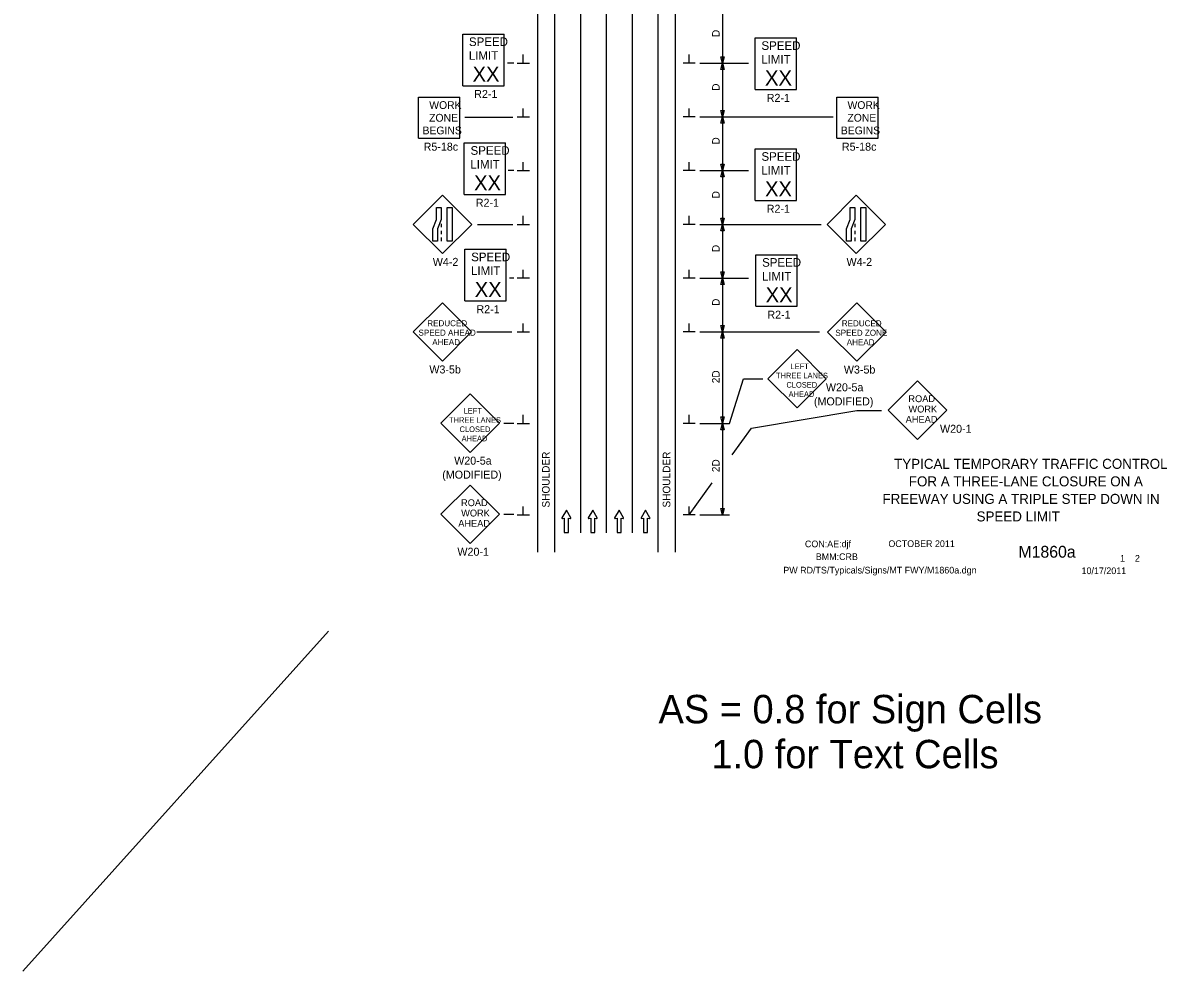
# Model space of a CAD drawing. Extents: x 16364 to 18480, y 5564 to 6927.
# Drawn here: x 16364 to 17427, y 5564 to 6446 of the extents above; entities that cross this region are included whole.
import ezdxf

# ---------------------------------------------------------------- set-up
doc = ezdxf.new("R2010")
doc.units = 0
for name, color, linetype in [('ALI_LEGAL_EX', 7, 'Continuous'), ('BORDER', 7, 'Continuous'), ('BORDER_SIGNAL_WO', 7, 'Continuous'), ('MT_SCRATCH_LEVEL_E', 7, 'Continuous'), ('PAVT_EDGE_EX', 7, 'Continuous'), ('TRAFFIC_SIGNS_PR', 7, 'Continuous'), ('TYPICAL_TEXT_DIMEN_PR', 7, 'Continuous')]:
    doc.layers.add(name, color=color, linetype=linetype)

msp = doc.modelspace()

# ---------------------------------------------------------------- linework, layer by layer
at = {"layer": 'ALI_LEGAL_EX'}
for p, q in [((16882, 6876.4), (16882, 5996.4)), ((16906, 6876.4), (16906, 5996.4)), ((16930, 6876.4), (16930, 5996.4))]:
    msp.add_line(p, q, dxfattribs=at)
for points in [[(16882, 6396.5), (16882, 6371.5)], [(16906, 6396.5), (16906, 6371.5)], [(16930, 6396.5), (16930, 6371.5)], [(16882, 6296.5), (16882, 6271.5)], [(16906, 6296.5), (16906, 6271.5)], [(16930, 6296.5), (16930, 6271.5)], [(16882, 6196.5), (16882, 6171.5)], [(16906, 6196.5), (16906, 6171.5)], [(16930, 6196.5), (16930, 6171.5)], [(16882, 6096.5), (16882, 6071.5)], [(16906, 6096.5), (16906, 6071.5)], [(16930, 6096.5), (16930, 6071.5)], [(16882, 5996.5), (16882, 5971.5)], [(16906, 5996.5), (16906, 5971.5)], [(16930, 5996.5), (16930, 5971.5)]]:
    msp.add_lwpolyline(points, dxfattribs=at)
at = {"layer": 'MT_SCRATCH_LEVEL_E'}
for p, q in [((16868.9, 5992.7), (16864.8, 5985.5)), ((16873, 5985.5), (16868.9, 5992.7)), ((16893.4, 5992.7), (16889.3, 5985.5)), ((16897.6, 5985.5), (16893.4, 5992.7)), ((16917.9, 5992.7), (16913.8, 5985.5)), ((16922.1, 5985.5), (16917.9, 5992.7)), ((16942.5, 5992.7), (16938.4, 5985.5)), ((16946.6, 5985.5), (16942.5, 5992.7)), ((16865.2, 5984.8), (16867, 5985.1)), ((16867, 5985.1), (16867, 5971.9)), ((16870.8, 5971.9), (16870.8, 5985.1)), ((16870.8, 5985.1), (16872.5, 5984.8)), ((16889.8, 5984.8), (16891.6, 5985.1)), ((16891.6, 5985.1), (16891.6, 5971.9)), ((16895.3, 5971.9), (16895.3, 5985.1)), ((16895.3, 5985.1), (16897.1, 5984.8)), ((16914.3, 5984.8), (16916.1, 5985.1)), ((16916.1, 5985.1), (16916.1, 5971.9)), ((16919.8, 5971.9), (16919.8, 5985.1)), ((16919.8, 5985.1), (16921.6, 5984.8)), ((16938.9, 5984.8), (16940.6, 5985.1)), ((16940.6, 5985.1), (16940.6, 5971.9)), ((16944.4, 5971.9), (16944.4, 5985.1)), ((16944.4, 5985.1), (16946.2, 5984.8)), ((16867, 5971.9), (16870.8, 5971.9)), ((16891.6, 5971.9), (16895.3, 5971.9)), ((16916.1, 5971.9), (16919.8, 5971.9)), ((16940.6, 5971.9), (16944.4, 5971.9))]:
    msp.add_line(p, q, dxfattribs=at)
for centre, start, end in [((16865.2, 5985.3), 150.4248, 279.9638), ((16872.6, 5985.3), 260.0362, 29.7731), ((16889.7, 5985.3), 150.4248, 279.9638), ((16897.1, 5985.3), 260.0362, 29.7731), ((16914.2, 5985.3), 150.4248, 279.9638), ((16921.7, 5985.3), 260.0362, 29.7731), ((16938.8, 5985.3), 150.4248, 279.9638), ((16946.2, 5985.3), 260.0362, 29.7731)]:
    msp.add_arc(centre, 0.463, start, end, dxfattribs=at)
at = {"layer": 'PAVT_EDGE_EX'}
for p, q in [((16842, 6926.7), (16842, 5953.6)), ((16858, 6926.7), (16858, 5953.6)), ((16954, 6926.7), (16954, 5953.6)), ((16970, 6926.7), (16970, 5953.6))]:
    msp.add_line(p, q, dxfattribs=at)
at = {"layer": 'TRAFFIC_SIGNS_PR'}
for p, q in [((16772.6, 6435.2), (16811, 6435.2)), ((16772.6, 6387.2), (16772.6, 6435.2)), ((16811, 6387.2), (16811, 6435.2)), ((17044.5, 6431.6), (17082.9, 6431.6)), ((17044.5, 6383.6), (17044.5, 6431.6)), ((17082.9, 6383.6), (17082.9, 6431.6)), ((16772.6, 6387.2), (16811, 6387.2)), ((17044.5, 6383.6), (17082.9, 6383.6)), ((16731.4, 6338.3), (16731.4, 6376.7)), ((16731.4, 6376.7), (16769.8, 6376.7)), ((16769.8, 6338.3), (16769.8, 6376.7)), ((17120.3, 6338.3), (17120.3, 6376.7)), ((17120.3, 6376.7), (17158.7, 6376.7)), ((17158.7, 6338.3), (17158.7, 6376.7)), ((16731.4, 6338.3), (16769.8, 6338.3)), ((16774, 6334.1), (16812.4, 6334.1)), ((16774, 6286.1), (16774, 6334.1)), ((16812.4, 6286.1), (16812.4, 6334.1)), ((17120.3, 6338.3), (17158.7, 6338.3)), ((17044.5, 6328.5), (17082.9, 6328.5)), ((17044.5, 6280.5), (17044.5, 6328.5)), ((17082.9, 6280.5), (17082.9, 6328.5)), ((16753.7, 6285.4), (16726.6, 6258.3)), ((16780.9, 6258.3), (16753.7, 6285.4)), ((16774, 6286.1), (16812.4, 6286.1)), ((17044.5, 6280.5), (17082.9, 6280.5)), ((17138.4, 6285.4), (17111.3, 6258.3)), ((17165.6, 6258.3), (17138.4, 6285.4)), ((16726.6, 6258.3), (16753.7, 6231.1)), ((16752.5, 6258.8), (16752.5, 6255.6)), ((16753.7, 6231.1), (16780.9, 6258.3)), ((17111.3, 6258.3), (17138.4, 6231.1)), ((17137.2, 6258.8), (17137.2, 6255.6)), ((17138.4, 6231.1), (17165.6, 6258.3)), ((16752.5, 6252.4), (16752.5, 6249.2)), ((16752.5, 6246), (16752.5, 6242.8)), ((17137.2, 6252.4), (17137.2, 6249.2)), ((17137.2, 6246), (17137.2, 6242.8)), ((16774.6, 6235.1), (16813, 6235.1)), ((16774.6, 6187.1), (16774.6, 6235.1)), ((16813, 6187.1), (16813, 6235.1)), ((17045.1, 6230.1), (17083.5, 6230.1)), ((17045.1, 6182.1), (17045.1, 6230.1)), ((17083.5, 6182.1), (17083.5, 6230.1)), ((16753.6, 6185.4), (16726.4, 6158.3)), ((16780.7, 6158.3), (16753.6, 6185.4)), ((16774.6, 6187.1), (16813, 6187.1)), ((17045.1, 6182.1), (17083.5, 6182.1)), ((17139, 6185.3), (17111.8, 6158.2)), ((17166.1, 6158.2), (17139, 6185.3)), ((16726.4, 6158.3), (16753.6, 6131.1)), ((16753.6, 6131.1), (16780.7, 6158.3)), ((17111.8, 6158.2), (17139, 6131)), ((17139, 6131), (17166.1, 6158.2)), ((17083.4, 6141.9), (17056.2, 6114.8)), ((17110.5, 6114.8), (17083.4, 6141.9)), ((17056.2, 6114.8), (17083.4, 6087.6)), ((17083.4, 6087.6), (17110.5, 6114.8)), ((17195.4, 6112.7), (17168.2, 6085.5)), ((17222.6, 6085.5), (17195.4, 6112.7)), ((16779.5, 6100.6), (16752.3, 6073.5)), ((16806.6, 6073.5), (16779.5, 6100.6)), ((17168.2, 6085.5), (17195.4, 6058.3)), ((17195.4, 6058.3), (17222.6, 6085.5)), ((16752.3, 6073.5), (16779.5, 6046.3)), ((16779.5, 6046.3), (16806.6, 6073.5)), ((16779.4, 6015.9), (16752.3, 5988.8)), ((16806.6, 5988.8), (16779.4, 6015.9)), ((16752.3, 5988.8), (16779.4, 5961.6)), ((16779.4, 5961.6), (16806.6, 5988.8))]:
    msp.add_line(p, q, dxfattribs=at)
for points in [[(16752.5, 6274), (16752.5, 6262.9), (16749.2, 6254), (16749.2, 6242.8), (16744.7, 6242.8), (16744.7, 6254), (16748, 6262.9), (16748, 6274)], [(16762.6, 6274), (16762.6, 6242.8), (16758.1, 6242.8), (16758.1, 6274)], [(17137.2, 6274), (17137.2, 6262.9), (17133.8, 6254), (17133.8, 6242.8), (17129.3, 6242.8), (17129.3, 6254), (17132.7, 6262.9), (17132.7, 6274)], [(17147.3, 6274), (17147.3, 6242.8), (17142.8, 6242.8), (17142.8, 6274)]]:
    msp.add_lwpolyline(points, close=True, dxfattribs=at)
at = {"layer": 'TYPICAL_TEXT_DIMEN_PR'}
for p, q in [((17014, 6458.3), (17014, 6408.3)), ((16828.8, 6408.3), (16828.8, 6416.1)), ((16983.1, 6408.3), (16983.1, 6416.1)), ((16820.2, 6408.3), (16814.3, 6408.3)), ((16823.2, 6408.3), (16834.5, 6408.3)), ((16988.7, 6408.3), (16977.5, 6408.3)), ((16993, 6408.3), (17038.1, 6408.3)), ((17014, 6408.3), (17012.4, 6414.2)), ((17012.4, 6414.2), (17014, 6414.2)), ((17012.4, 6402.4), (17014, 6408.3)), ((17014, 6414.2), (17015.5, 6414.2)), ((17015.5, 6414.2), (17014, 6408.3)), ((17014, 6408.3), (17014, 6358.3)), ((17014, 6408.3), (17015.5, 6402.4)), ((17014, 6402.4), (17012.4, 6402.4)), ((17015.5, 6402.4), (17014, 6402.4)), ((16828.8, 6358.3), (16828.8, 6366.1)), ((16983.1, 6358.3), (16983.1, 6366.1)), ((17014, 6358.3), (17012.4, 6364.2)), ((17012.4, 6364.2), (17014, 6364.2)), ((17014, 6364.2), (17015.5, 6364.2)), ((17015.5, 6364.2), (17014, 6358.3)), ((16774.6, 6357.9), (16819, 6357.9)), ((16823.2, 6358.3), (16834.5, 6358.3)), ((16988.7, 6358.3), (16977.5, 6358.3)), ((16993, 6358.3), (17117, 6358.3)), ((17012.4, 6352.4), (17014, 6358.3)), ((17014, 6352.4), (17012.4, 6352.4)), ((17014, 6358.3), (17014, 6308.3)), ((17014, 6358.3), (17015.5, 6352.4)), ((17015.5, 6352.4), (17014, 6352.4)), ((16828.8, 6308.3), (16828.8, 6316.1)), ((16983.1, 6308.3), (16983.1, 6316.1)), ((17014, 6308.3), (17012.4, 6314.2)), ((17012.4, 6314.2), (17014, 6314.2)), ((17014, 6314.2), (17015.5, 6314.2)), ((17015.5, 6314.2), (17014, 6308.3)), ((16820.2, 6308.3), (16814.8, 6308.3)), ((16823.2, 6308.3), (16834.5, 6308.3)), ((16988.7, 6308.3), (16977.5, 6308.3)), ((16993, 6308.3), (17038.1, 6308.3)), ((17012.4, 6302.4), (17014, 6308.3)), ((17014, 6302.4), (17012.4, 6302.4)), ((17014, 6308.3), (17015.5, 6302.4)), ((17014, 6308.3), (17014, 6258.3)), ((17015.5, 6302.4), (17014, 6302.4)), ((16786.4, 6258.3), (16819, 6258.3)), ((16823.2, 6258.3), (16834.5, 6258.3)), ((16828.8, 6258.3), (16828.8, 6266.1)), ((16988.7, 6258.3), (16977.5, 6258.3)), ((16983.1, 6258.3), (16983.1, 6266.1)), ((16993, 6258.3), (17105.8, 6258.3)), ((17014, 6258.3), (17012.4, 6264.2)), ((17012.4, 6264.2), (17014, 6264.2)), ((17012.4, 6252.4), (17014, 6258.3)), ((17014, 6264.2), (17015.5, 6264.2)), ((17015.5, 6264.2), (17014, 6258.3)), ((17014, 6258.3), (17015.5, 6252.4)), ((17014, 6258.3), (17014, 6208.3)), ((17014, 6252.4), (17012.4, 6252.4)), ((17015.5, 6252.4), (17014, 6252.4)), ((16828.8, 6208.3), (16828.8, 6216.1)), ((16983.1, 6208.3), (16983.1, 6216.1)), ((17014, 6208.3), (17012.4, 6214.2)), ((17012.4, 6214.2), (17014, 6214.2)), ((17014, 6214.2), (17015.5, 6214.2)), ((17015.5, 6214.2), (17014, 6208.3)), ((16820.2, 6208.3), (16815.9, 6208.3)), ((16834.5, 6208.3), (16823.2, 6208.3)), ((16988.7, 6208.3), (16977.5, 6208.3)), ((16993, 6208.3), (17038.1, 6208.3)), ((17012.4, 6202.4), (17014, 6208.3)), ((17014, 6202.4), (17012.4, 6202.4)), ((17014, 6208.3), (17014, 6158.3)), ((17014, 6208.3), (17015.5, 6202.4)), ((17015.5, 6202.4), (17014, 6202.4)), ((16828.8, 6158.3), (16828.8, 6166.1)), ((16983.1, 6158.3), (16983.1, 6166.1)), ((17014, 6158.3), (17012.4, 6164.2)), ((17012.4, 6164.2), (17014, 6164.2)), ((17014, 6164.2), (17015.5, 6164.2)), ((17015.5, 6164.2), (17014, 6158.3)), ((16785.6, 6158.3), (16818.3, 6158.3)), ((16823.2, 6158.3), (16834.5, 6158.3)), ((16988.7, 6158.3), (16977.5, 6158.3)), ((16993, 6158.3), (17104.1, 6158.3)), ((17012.4, 6152.4), (17014, 6158.3)), ((17014, 6152.4), (17012.4, 6152.4)), ((17014, 6158.3), (17014, 6073.3)), ((17014, 6158.3), (17015.5, 6152.4)), ((17015.5, 6152.4), (17014, 6152.4)), ((17020.5, 6073.3), (17033.5, 6114.8)), ((17033.5, 6114.8), (17051.6, 6114.8)), ((16828.8, 6073.3), (16828.8, 6081.1)), ((16983.1, 6073.3), (16983.1, 6081.1)), ((17014, 6073.3), (17012.4, 6079.2)), ((17012.4, 6079.2), (17014, 6079.2)), ((17014, 6079.2), (17015.5, 6079.2)), ((17015.5, 6079.2), (17014, 6073.3)), ((17041, 6068.7), (17139.1, 6085.3)), ((17139.1, 6085.3), (17162, 6085.3)), ((16820.2, 6073.1), (16810.8, 6073.1)), ((16823.2, 6073.3), (16834.5, 6073.3)), ((16988.7, 6073.3), (16977.5, 6073.3)), ((16993, 6073.3), (17020.5, 6073.3)), ((17012.4, 6067.4), (17014, 6073.3)), ((17014, 6067.4), (17012.4, 6067.4)), ((17014, 6073.3), (17014, 5988.3)), ((17014, 6073.3), (17015.5, 6067.4)), ((17015.5, 6067.4), (17014, 6067.4)), ((17023.2, 6044), (17041, 6068.7)), ((16983.1, 5988.3), (17004.6, 6018.1)), ((16828.8, 5988.3), (16828.8, 5996.1)), ((16983.1, 5988.3), (16983.1, 5996.1)), ((17014, 5988.3), (17012.4, 5994.2)), ((17012.4, 5994.2), (17014, 5994.2)), ((17014, 5994.2), (17015.5, 5994.2)), ((17015.5, 5994.2), (17014, 5988.3)), ((16820.2, 5988.4), (16810.8, 5988.4)), ((16823.2, 5988.3), (16834.5, 5988.3)), ((16988.7, 5988.3), (16977.5, 5988.3)), ((16993, 5988.3), (17020.5, 5988.3)), ((16647.8, 5880), (16363.6, 5564))]:
    msp.add_line(p, q, dxfattribs=at)

# ---------------------------------------------------------------- texts
at = {"layer": 'BORDER'}
for s, p in [('TYPICAL TEMPORARY TRAFFIC CONTROL', (17173.6, 6031)), ('FOR A THREE-LANE CLOSURE ON A', (17187.3, 6014.7)), ('FREEWAY USING A TRIPLE STEP DOWN IN ', (17162.8, 5998.4)), ('SPEED LIMIT', (17250.3, 5982.1))]:
    msp.add_text(s, height=9.3, dxfattribs=at).set_placement(p)
at = {"layer": 'BORDER_SIGNAL_WO'}
for s, height, p in [('CON:AE:djf  ', 6.2, (17090.7, 5958.1)), ('    OCTOBER 2011', 6.2, (17159.1, 5958.3)), ('    M1860a   ', 11, (17272.9, 5948.4)), ('BMM:CRB', 6.2, (17100.8, 5946.2)), (' 1    2 ', 6.2, (17381.4, 5944.7)), ('PW RD/TS/Typicals/Signs/MT FWY/M1860a.dgn      ', 6.2, (17070.6, 5933.7)), ('10/17/2011', 6.2, (17347.9, 5933.1)), ('AS = 0.8 for Sign Cells', 26.424, (16954.6, 5794.4)), ('     1.0 for Text Cells', 26.424, (16954.6, 5752.6))]:
    msp.add_text(s, height=height, dxfattribs=at).set_placement(p)
at = {"layer": 'TRAFFIC_SIGNS_PR'}
for s, height, p in [('SPEED', 8, (16778.3, 6424.1)), ('SPEED', 8, (17050.3, 6420.5)), ('LIMIT', 8, (16778.2, 6411.3)), ('LIMIT', 8, (17050.1, 6407.7)), ('XX', 14.03, (16781.7, 6391)), ('XX', 14.03, (17053.6, 6387.4)), ('R2-1', 7.44, (16783.2, 6375.8)), ('WORK', 7.22, (16741.4, 6365.6)), ('R2-1', 7.44, (17055.2, 6372.2)), ('WORK', 7.22, (17130.3, 6365.6)), ('ZONE', 7.22, (16741.3, 6353.8)), ('ZONE', 7.22, (17130.2, 6353.8)), ('BEGINS', 7.22, (16735.2, 6342)), ('BEGINS', 7.22, (17124.1, 6342)), ('R5-18c', 7.44, (16736.2, 6326.8)), ('SPEED', 8, (16779.8, 6323)), ('R5-18c', 7.44, (17125.1, 6326.8)), ('SPEED', 8, (17050.3, 6317.4)), ('LIMIT', 8, (16779.6, 6310.2)), ('LIMIT', 8, (17050.1, 6304.6)), ('XX', 14.03, (16783.1, 6289.9)), ('XX', 14.03, (17053.6, 6284.3)), ('R2-1', 7.44, (16784.7, 6274.7)), ('R2-1', 7.44, (17055.2, 6269.1)), ('W4-2', 7.44, (16744.7, 6219.7)), ('SPEED', 8, (16780.4, 6224)), ('SPEED', 8, (17050.9, 6218.9)), ('W4-2', 7.44, (17129.4, 6219.7)), ('LIMIT', 8, (16780.2, 6211.2)), ('LIMIT', 8, (17050.7, 6206.1)), ('XX', 14.03, (16783.7, 6190.8)), ('XX', 14.03, (17054.2, 6185.8)), ('R2-1', 7.44, (16785.3, 6175.7)), ('R2-1', 7.44, (17055.8, 6170.6)), ('SPEED AHEAD', 5.6, (16731.4, 6154.8)), ('REDUCED', 5.6, (16739.6, 6163.6)), ('SPEED ZONE', 5.6, (17119, 6154.7)), ('REDUCED', 5.6, (17125, 6163.5)), ('AHEAD', 5.6, (16744.2, 6146)), ('AHEAD', 5.6, (17129.6, 6145.9)), ('LEFT', 5.2, (17077.3, 6123.7)), ('W3-5b', 7.44, (16741.5, 6119.7)), ('THREE LANES', 5.2, (17063.8, 6115.1)), ('W3-5b', 7.44, (17126.9, 6119.6)), ('CLOSED', 5.2, (17073.5, 6106.5)), ('W20-5a', 7.44, (17110.2, 6103.1)), ('AHEAD', 5.2, (17075.5, 6097.9)), ('(MODIFIED)', 7.44, (17099.1, 6090)), ('ROAD', 6.41, (17186.9, 6093)), ('LEFT', 5.2, (16773.4, 6082.4)), ('WORK', 6.41, (17187, 6083.4)), ('THREE LANES', 5.2, (16759.8, 6073.8)), ('AHEAD', 6.41, (17184.4, 6073.8)), ('CLOSED', 5.2, (16769.6, 6065.2)), ('W20-1', 7.45, (17216.3, 6064.5)), ('AHEAD', 5.2, (16771.5, 6056.6)), ('W20-5a', 7.44, (16764.6, 6034.9)), ('(MODIFIED)', 7.44, (16753.5, 6021.9)), ('ROAD', 6.4, (16771, 5996.3)), ('WORK', 6.4, (16771.1, 5986.7)), ('AHEAD', 6.4, (16768.4, 5977.1)), ('W20-1', 7.44, (16767.6, 5950.2))]:
    msp.add_text(s, height=height, dxfattribs=at).set_placement(p)
at = {"layer": 'TYPICAL_TEXT_DIMEN_PR'}
for s, p in [('D', (17011.4, 6432.5)), ('D', (17011.4, 6382.5)), ('D', (17011.4, 6332.5)), ('D', (17011.4, 6282.5)), ('D', (17011.4, 6232.5)), ('D', (17011.4, 6182.5)), ('2D', (17011.4, 6110.6)), ('SHOULDER', (16853.3, 5995)), ('SHOULDER', (16965.5, 5995)), ('2D', (17011.4, 6027.9))]:
    msp.add_text(s, height=7, rotation=90, dxfattribs=at).set_placement(p)

doc.saveas('drawing.dxf')
